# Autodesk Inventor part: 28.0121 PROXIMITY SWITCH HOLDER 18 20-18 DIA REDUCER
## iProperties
Created: 2007-05
Part Number: 28.0121 PROXIMITY SWITCH HOLDER 18 20-18 DIA REDUCER
Document SubType Name: Modeling
Designer: Andy Moles
Material: Acetal Resin, Black
Mass: 1.63084 g
Surface Area: 24.4534 cm^2
Volume: 1.14445 cm^3
Density: 1.425 g/cm^3
Author: Andy Moles
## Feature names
1. Extrusion1
